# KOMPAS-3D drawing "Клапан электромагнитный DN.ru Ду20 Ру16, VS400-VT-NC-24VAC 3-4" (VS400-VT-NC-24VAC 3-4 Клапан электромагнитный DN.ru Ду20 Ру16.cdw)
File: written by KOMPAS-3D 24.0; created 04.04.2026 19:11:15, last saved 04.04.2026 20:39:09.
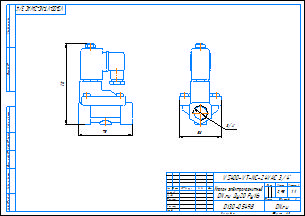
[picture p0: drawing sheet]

Document properties: c3d_UniqueCompID: ef56311e-7521-43dc-8291-0e6108b3d81d; Обозначение: VS400-ET-NC-220VAC 1-2; Наименование: Клапан электромагнитный DN.ru Ду15 Ру16; Автор: artio; Класс точности: c; Знак неуказанной шероховатости: Шероховатость не задана; Рассекать на разрезах: Да; c3d_UniqueCompID: ef56311e-7521-43dc-8291-0e6108b3d81d; Обозначение: VS400-ET-NC-220VAC 3-4; Наименование: Клапан электромагнитный DN.ru Ду20 Ру16; Автор: artio; Класс точности: c; Знак неуказанной шероховатости: Шероховатость не задана; Рассекать на разрезах: Да; c3d_UniqueCompID: ef56311e-7521-43dc-8291-0e6108b3d81d; Обозначение: VS400-ET-NC-220VAC 3-8; Наименование: Клапан электромагнитный DN.ru Ду10 Ру16; Автор: artio; Класс точности: c; Знак неуказанной шероховатости: Шероховатость не задана; Рассекать на разрезах: Да; Автор: artio; Форматы листов документа: A3; Полное имя файла: VS400-VT-NC-24VAC 3-4 Клапан электромагнитный DN.ru Ду20 Ру16.m3d; Масса: 0.954; Наименование: Клапан электромагнитный DN.ru Ду20 Ру16; Количество листов документа: 1; Примечание: D130-05498

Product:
- Body: Тело 1  | qty 1
    Масса: 1.210539
- Part/product: Клапан электромагнитный DN.ru Ду20 Ру16  | designation VS400-VT-NC-24VAC 3-4
    Масса: 0.954
    Раздел спецификации: Прочие изделия
    Примечание: D130-05498
    additional columns: ef56311e-7521-43dc-8291-0e6108b3d81d; VS400-ET-NC-220VAC 3-4; artio; c; Шероховатость не задана; Да

Views: Вид 1, Спереди, Проекционный вид 2
Referenced files in C:\Users\artio\OneDrive\Рабочий стол\Клапан электромагнитный DN.ru\VS400-ET-NC\VS400-ET-NC-24VDC\: VS400-ET-NC-24VDC 3-8 Клапан электромагнитный DN.ru Ду10 Ру16.m3d
Referenced files in C:\Users\artio\OneDrive\Рабочий стол\Клапан электромагнитный DN.ru\VS400-VT-NC\VS400-VT-NC-24VAC\: VS400-VT-NC-24VAC 3-4 Клапан электромагнитный DN.ru Ду20 Ру16.m3d
Referenced files in C:\Users\artio\OneDrive\Рабочий стол\Клапан электромагнитный DN.ru\VS400-ET-NC\: VS400-ET-NC-24VDC 3-8 Клапан электромагнитный DN.ru Ду10 Ру16.cdw
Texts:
  VS400-VT-NC-24VAC 3-4
  Клапан электромагнитный
  DN.ru Ду20 Ру16
  VS400-VT-NC-24VAC 3/4"
  VS400-VT-NC-24VAC 3/4"-
  Клапан электромагнитный DN.ru Ду20 Ру16
  VS400-VT-NC-24VAC 3-4 Клапан электромагнитный DN.ru Ду20 Ру16
Dimensions and other numbers on the sheet: 0; 3; 2; 4; 58; 3/4"; 75; 112; 1:1; 1; 0,95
